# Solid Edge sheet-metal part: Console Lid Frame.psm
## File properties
Author: m_hel
Template: Iso Metric Sheet Metal.psm
Last saved by: m_hel
Revision: 4
Application: Solid Edge
Accuracy: 0,990
Material Thickness: 0,50 cm
Bend Radius: 0,10 cm
Relief Width: 0,10 cm
Relief Length: 0,00 cm
Neutral Factor: 0,330
Minimum Arc Length: 0,01 cm
Deviational Tolerance: 0,01 cm
Username: m_hel
Material: Chrome
Face Style: Chrome
Fill Style: Normal
Virtual Style: Normal
Grouping: Uncategorized
LibraryName: Custom Materials
Coef. of Thermal Exp: 0.0
Thermal Conductivity: 0.0
Specific Heat: 0.0
Modulus of Elasticity: 0.0
Poisson's Ratio: 0.0
Yield Stress: 0.0
Ultimate Stress: 0.0
Elongation: 0.0
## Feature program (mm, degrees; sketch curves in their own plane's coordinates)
base tab "unnamed BaseTab 1"
flange "Flange_1"
flange "Flange_2"
flange "Flange_3"
flange "Flange_4"
dimple "Dimple_1"
sketch for "unnamed Cutout 1" plane through (0, 0, -15) normal (0, 0, 1) x-axis (-1, 0, 0)
  line (-160, -160) -> (160, -160)
  line (160, -160) -> (160, 160)
  line (160, 160) -> (-160, 160)
  line (-160, 160) -> (-160, -160)
  dimension (linear) = 160
extrude "unnamed Cutout 1" cut
close corner "CloseCorner_2"
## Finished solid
Body 1: solid body, 60 faces, 136 edges, 80 vertices.
  Faces by surface: plane 44, cylinder 16
  Edges by curve: line 104, ellipse 24, circle 8
Bounding box of the edges (mm): 450.000 x 450.000 x 25.000, from (-225, -225, -20) to (225, 225, 5).
Cylindrical faces by radius (mm): R1 x4, R5 x8, R6 x4
Planar faces by outward normal: +x 7, +y 7, +z 2, -x 7, -y 7, -z 6, oblique 8
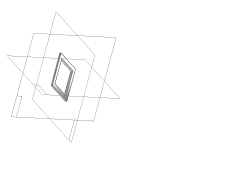
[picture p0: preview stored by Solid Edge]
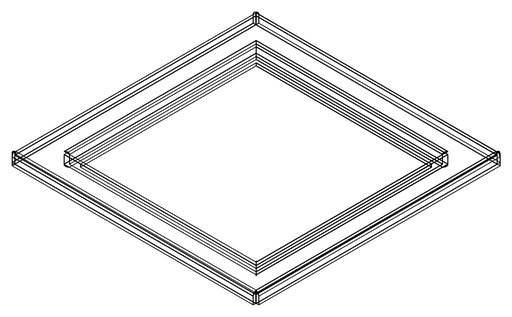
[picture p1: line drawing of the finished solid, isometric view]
